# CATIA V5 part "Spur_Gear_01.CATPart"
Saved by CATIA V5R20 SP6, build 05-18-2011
Part number: Spur_Gear_01
Bounding box of the stored display mesh (mm): x 21 to 25, y -7.531 to 7.62, z 5.585 to 20.748
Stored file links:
  E:\#01 CATIA Lecture Materials\#06 DMU\#16 DMU Page01 KIN EX16\Spur_Gear_01.CATPart
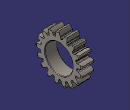
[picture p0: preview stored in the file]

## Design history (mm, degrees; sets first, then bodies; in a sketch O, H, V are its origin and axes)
Set1
  Sketch1, origin (0, 0, 0), H (0, 1, 0), V (0, 0, 1), geometry linked from another document
Body1 (main body)
Body2
  Solid1: solid without history
  Translate1: Direction Sketch1, Length 3.15, ToTransfor Solid1
  Sketch2 on face of Solid1, origin (25.5, 3.6778, 14.0071), H (0, 1, 0), V (0, 0, 1)
    point P1 (-3.6089, -0.8573)
    reference projected circle E1 centre (-3.6089, -0.8573) radius 4.5 from edge [face of Solid1 | face of Solid1]
    concentricity: E1 P1
  Hole1: placed by Sketch2, at (25.5, 0.069, 13.1498) direction (-1, 0, 0), diameter 9, through (limit type 6)
  Chamfer1: length 0.15, angle 45, on edge [face of Solid1 | face of Hole1]; edge [face of Hole1 | face of Solid1]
